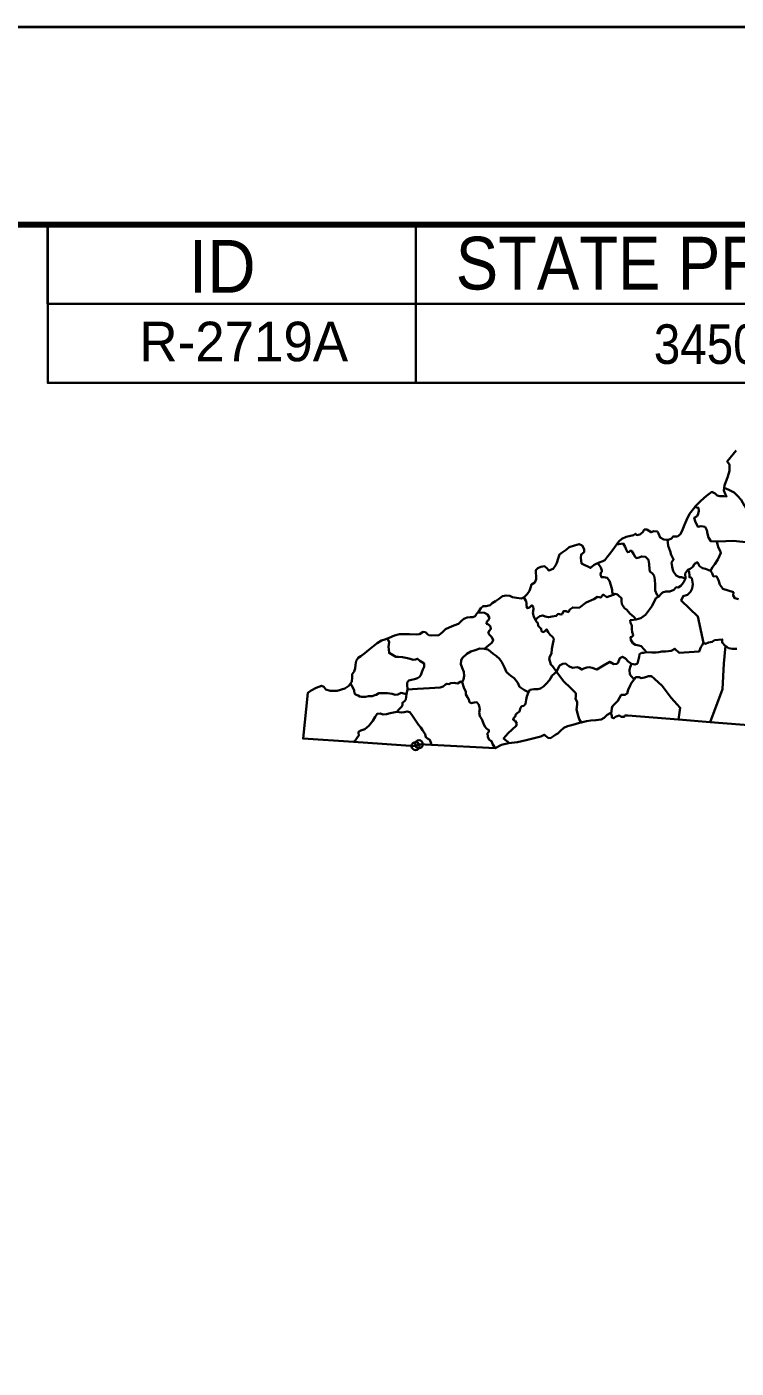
# Model space of a CAD drawing. Extents: x -9.2 to 11.5, y -0.7 to 11.8.
# Drawn here: x 4.396 to 5.741, y 8.457 to 11 of the extents above; entities that cross this region are included whole.
import ezdxf
from ezdxf.enums import TextEntityAlignment as Align

# ---------------------------------------------------------------- set-up
doc = ezdxf.new("R2010")
doc.units = 0
doc.header["$LTSCALE"] = 0.03
doc.header["$PDMODE"] = 32
doc.header["$PDSIZE"] = 0.015
doc.layers.add('1', color=7, linetype='Continuous', lineweight=35)
doc.layers.add('63', color=7, linetype='Continuous', lineweight=35)

msp = doc.modelspace()

# ---------------------------------------------------------------- linework, layer by layer
at = {"layer": '1'}
for p, q in [((4.435, 10.625), (4.435, 10.475)), ((5.1335, 10.626), (5.1335, 10.325)), ((4.435, 10.475), (8.135, 10.475))]:
    msp.add_line(p, q, dxfattribs=at)
at = {"layer": '1', "lineweight": 40}
msp.add_lwpolyline([(-8.5, 11), (8.5, 11), (8.5, 0), (-8.5, 0)], close=True, dxfattribs=at)
at = {"layer": '1', "lineweight": 158}
msp.add_lwpolyline([(0.625, 10.625), (8.135, 10.625), (8.135, 0.375), (0.625, 0.375)], close=True, dxfattribs=at)
at = {"layer": '1'}
msp.add_lwpolyline([(4.4355, 10.625), (8.135, 10.625), (8.135, 10.325), (4.4355, 10.325)], close=True, dxfattribs=at)
at = {"layer": '63'}
for p, q in [((5.5197, 9.8015), (5.5221, 9.8039)), ((5.1181, 9.7438), (5.1157, 9.7349)), ((5.533, 9.7353), (5.5346, 9.7368)), ((5.1332, 9.6364), (5.1395, 9.64)), ((5.1332, 9.6364), (5.1395, 9.64))]:
    msp.add_line(p, q, dxfattribs=at)
for points in [[(5.7412, 10.1971), (5.724, 10.1759), (5.7283, 10.1706), (5.7288, 10.1582), (5.7253, 10.1476), (5.7192, 10.1305), (5.7185, 10.1261), (5.7178, 10.1211), (5.7206, 10.1145), (5.7229, 10.1098), (5.7174, 10.1104), (5.7104, 10.1104), (5.705, 10.1114), (5.7015, 10.1153), (5.695, 10.1183), (5.6849, 10.1107), (5.6742, 10.1013), (5.6632, 10.0904), (5.6625, 10.0894), (5.6527, 10.0766), (5.647, 10.0647), (5.6431, 10.0558), (5.6395, 10.0462), (5.6354, 10.038), (5.6298, 10.0339), (5.6214, 10.034), (5.6187, 10.0301), (5.6126, 10.0273), (5.6112, 10.0274), (5.6042, 10.0279), (5.5968, 10.0317), (5.5941, 10.0393), (5.5918, 10.0434), (5.5848, 10.0436), (5.5797, 10.042), (5.5719, 10.0469), (5.5667, 10.0469), (5.5639, 10.0421), (5.5583, 10.0376), (5.5526, 10.0366), (5.5505, 10.039), (5.5466, 10.0362), (5.5382, 10.0347), (5.5323, 10.0331), (5.5245, 10.0295), (5.5195, 10.0248), (5.5144, 10.0184), (5.5136, 10.0174), (5.5074, 10.0088), (5.5011, 10.0006), (5.4958, 9.9938), (5.4919, 9.989), (5.488, 9.9872), (5.4816, 9.9847), (5.4786, 9.9835), (5.4845, 9.9749), (5.4866, 9.9693), (5.4862, 9.9671), (5.4845, 9.9652), (5.4839, 9.9619), (5.4856, 9.9564), (5.4901, 9.9568), (5.4965, 9.9556), (5.501, 9.9495), (5.5033, 9.9417), (5.5058, 9.9328), (5.5062, 9.9289), (5.5076, 9.9234)], [(5.7185, 10.1261), (5.727, 10.122), (5.7371, 10.1169), (5.7437, 10.1108), (5.7509, 10.1034), (5.7571, 10.0919), (5.7608, 10.0864), (5.7647, 10.0807), (5.7692, 10.0833), (5.7762, 10.0762), (5.782, 10.0696), (5.7904, 10.0663)], [(5.7048, 10.0241), (5.6929, 10.0249), (5.6884, 10.0317), (5.6871, 10.0386), (5.6853, 10.046), (5.6822, 10.052), (5.6746, 10.0534), (5.6686, 10.0519), (5.6635, 10.0626), (5.6614, 10.069), (5.6669, 10.0725), (5.669, 10.077), (5.6704, 10.0827), (5.67, 10.0879), (5.6625, 10.0893)], [(5.2464, 9.883), (5.2487, 9.8867), (5.2489, 9.8871), (5.2524, 9.8912), (5.2567, 9.8982), (5.2612, 9.9019), (5.2669, 9.9015), (5.2745, 9.9038), (5.2786, 9.9075), (5.2846, 9.9112), (5.2903, 9.9153), (5.2983, 9.9204), (5.3049, 9.9221), (5.3117, 9.9213), (5.3172, 9.9188), (5.3248, 9.9176), (5.3343, 9.9162), (5.3394, 9.9189), (5.3447, 9.9244), (5.349, 9.9306), (5.3509, 9.9368), (5.3529, 9.9425), (5.3593, 9.9468), (5.3619, 9.953), (5.3617, 9.9588), (5.3613, 9.9651), (5.3615, 9.97), (5.3652, 9.9739), (5.3707, 9.9764), (5.3777, 9.9773), (5.3822, 9.9738), (5.3859, 9.9691), (5.3943, 9.9722), (5.3984, 9.9787), (5.4009, 9.9841), (5.4033, 9.9919), (5.4058, 9.9995), (5.4109, 10.0032), (5.4185, 10.0087), (5.4246, 10.0133), (5.4345, 10.017), (5.4433, 10.0193), (5.4493, 10.0166), (5.4532, 10.0098), (5.4528, 10.0043), (5.4471, 9.9996), (5.4465, 9.9934), (5.4479, 9.9825), (5.465, 9.9742), (5.4716, 9.9803), (5.4771, 9.9828), (5.4786, 9.9834)], [(5.5945, 9.9202), (5.5904, 9.9237), (5.5873, 9.9315), (5.5873, 9.943), (5.5867, 9.9516), (5.5854, 9.9592), (5.5823, 9.9637), (5.5772, 9.9676), (5.5768, 9.9719), (5.5761, 9.9816), (5.5747, 9.9898), (5.5693, 9.9951), (5.5617, 9.9959), (5.557, 9.9938), (5.5521, 9.993), (5.5494, 9.9953), (5.5465, 10.0008), (5.5434, 10.0057), (5.5409, 10.0071), (5.5381, 10.0045), (5.5352, 10.0038), (5.5327, 10.0092), (5.5309, 10.0141), (5.5269, 10.0205), (5.5228, 10.02), (5.5143, 10.0184)], [(5.6112, 10.0273), (5.612, 10.0163), (5.6157, 10.0059), (5.6182, 9.9991), (5.6209, 9.9929), (5.6225, 9.9901), (5.6184, 9.9843), (5.6195, 9.9765), (5.6216, 9.9683), (5.6275, 9.9597), (5.6339, 9.9566), (5.6378, 9.9568), (5.6452, 9.954)], [(5.7048, 10.0241), (5.7059, 10.0188), (5.7079, 10.0126), (5.7104, 10.0081), (5.7119, 10.003), (5.7098, 9.9972), (5.7062, 9.99), (5.7008, 9.9814), (5.6965, 9.9756), (5.6922, 9.9684)], [(5.7708, 10.0224), (5.7659, 10.0224), (5.7354, 10.0256), (5.7215, 10.0252), (5.7048, 10.0241)], [(5.6922, 9.9685), (5.6828, 9.9726), (5.6774, 9.9736), (5.6719, 9.9773), (5.6677, 9.9851), (5.6622, 9.9818), (5.6587, 9.9766), (5.6542, 9.9727), (5.6495, 9.9709), (5.6522, 9.967), (5.6528, 9.9594), (5.6524, 9.9567), (5.6555, 9.9561), (5.6569, 9.9545), (5.658, 9.9512), (5.659, 9.9434), (5.6576, 9.9354), (5.6543, 9.9288), (5.6486, 9.9231), (5.6406, 9.921), (5.6371, 9.9126), (5.6684, 9.8824), (5.679, 9.8322), (5.6765, 9.8279), (5.6743, 9.8238), (5.671, 9.816), (5.6332, 9.8132), (5.625, 9.821), (5.6182, 9.8173), (5.6131, 9.8167), (5.6073, 9.8158), (5.6003, 9.816), (5.5946, 9.8148), (5.589, 9.8137), (5.581, 9.8137), (5.571, 9.8145), (5.5664, 9.8196), (5.5613, 9.8256), (5.5568, 9.827), (5.55, 9.8284), (5.5453, 9.8315), (5.5413, 9.8377), (5.5409, 9.843), (5.5432, 9.8436), (5.5452, 9.8457), (5.5456, 9.8477), (5.5442, 9.8522), (5.5435, 9.8588), (5.5431, 9.8648), (5.5408, 9.8703), (5.5402, 9.875), (5.5423, 9.8754), (5.5517, 9.8765), (5.5474, 9.8814), (5.5396, 9.8877), (5.5338, 9.8945), (5.5293, 9.8982), (5.5241, 9.9058), (5.5235, 9.9117), (5.5235, 9.9171), (5.5194, 9.921), (5.5161, 9.9236), (5.5109, 9.9248), (5.5076, 9.9234), (5.4959, 9.9186), (5.489, 9.9236), (5.4844, 9.918), (5.4783, 9.9194), (5.4711, 9.9149), (5.4567, 9.9087), (5.4432, 9.8988), (5.4311, 9.8994), (5.4255, 9.8951), (5.4253, 9.8941), (5.4229, 9.8904), (5.4186, 9.8922), (5.4134, 9.8922), (5.411, 9.8863), (5.4087, 9.8862), (5.4034, 9.8871), (5.3999, 9.8834), (5.3923, 9.8819), (5.3892, 9.8817), (5.3855, 9.8807), (5.3791, 9.8821), (5.3742, 9.8843), (5.3691, 9.8829), (5.3642, 9.8794), (5.3603, 9.8759), (5.3572, 9.8816), (5.3557, 9.8888), (5.3571, 9.896), (5.3559, 9.9009), (5.3532, 9.903), (5.3493, 9.8993), (5.3456, 9.8978), (5.3436, 9.9013), (5.3435, 9.9066), (5.3429, 9.9112), (5.3386, 9.9183)], [(5.6495, 9.9708), (5.6446, 9.9634), (5.6452, 9.954)], [(5.7456, 9.9152), (5.7386, 9.9167), (5.7355, 9.9218), (5.7361, 9.9282), (5.7161, 9.9349), (5.7102, 9.9425), (5.7075, 9.9511), (5.7036, 9.9583), (5.698, 9.9581), (5.6966, 9.9603), (5.6955, 9.964), (5.6941, 9.9663), (5.6922, 9.9685)], [(5.6452, 9.954), (5.6415, 9.9464), (5.636, 9.94), (5.6311, 9.9369), (5.6276, 9.9375), (5.6227, 9.9324), (5.6155, 9.9297), (5.6079, 9.9297), (5.6017, 9.9274), (5.5987, 9.9249), (5.5945, 9.9202)], [(5.5517, 9.8764), (5.5601, 9.8791), (5.569, 9.8853), (5.5769, 9.8951), (5.5819, 9.9025), (5.5868, 9.913), (5.5896, 9.9173), (5.5945, 9.9202)], [(5.2464, 9.883), (5.2419, 9.8807), (5.2366, 9.8809), (5.2312, 9.8805), (5.2249, 9.8776), (5.2201, 9.8737), (5.2146, 9.8684), (5.2058, 9.8648), (5.1966, 9.8611), (5.1896, 9.858), (5.184, 9.8527), (5.1771, 9.8465), (5.1635, 9.8459), (5.1586, 9.8469), (5.1563, 9.8481), (5.1518, 9.8522), (5.1477, 9.853), (5.1409, 9.8487), (5.1341, 9.8481), (5.1214, 9.8485), (5.1109, 9.8486), (5.1029, 9.8486), (5.0933, 9.8464), (5.0832, 9.842), (5.08, 9.8406)], [(5.2638, 9.8206), (5.272, 9.8278), (5.2776, 9.8323), (5.2806, 9.8373), (5.2779, 9.843), (5.2732, 9.8471), (5.2711, 9.8514), (5.2732, 9.8557), (5.2761, 9.8586), (5.275, 9.8629), (5.2717, 9.8668), (5.2678, 9.8685), (5.2684, 9.8726), (5.2707, 9.8748), (5.2733, 9.8793), (5.2696, 9.8861), (5.2637, 9.8888), (5.2515, 9.8896)], [(5.4003, 9.7774), (5.3933, 9.7874), (5.3896, 9.7909), (5.3863, 9.8016), (5.3877, 9.8065), (5.3908, 9.8118), (5.3916, 9.8209), (5.3934, 9.8305), (5.3947, 9.8363), (5.3953, 9.8398), (5.393, 9.8439), (5.3883, 9.8473), (5.3843, 9.8525), (5.3815, 9.8576), (5.3778, 9.8539), (5.3745, 9.8527), (5.372, 9.8543), (5.3716, 9.859), (5.3679, 9.8617), (5.3654, 9.8645), (5.3648, 9.8699), (5.3625, 9.8723), (5.3603, 9.8758)], [(5.08, 9.8406), (5.0746, 9.8383), (5.0682, 9.8367), (5.06, 9.8313), (5.0506, 9.8243), (5.0444, 9.8192), (5.0366, 9.8126), (5.0292, 9.8072), (5.0241, 9.8041), (5.0204, 9.7978), (5.019, 9.7904), (5.0188, 9.7838), (5.0164, 9.7778), (5.0129, 9.7729), (5.0131, 9.767), (5.0121, 9.7585), (5.0096, 9.7551), (5.0064, 9.7507), (4.999, 9.7458), (4.9844, 9.7412), (4.9711, 9.741), (4.9632, 9.7439), (4.9591, 9.7486), (4.955, 9.7508), (4.9443, 9.7471), (4.9353, 9.7418), (4.9287, 9.7374), (4.9197, 9.6506), (5.0155, 9.6443), (5.1332, 9.6364)], [(5.08, 9.8406), (5.0828, 9.8334), (5.0818, 9.8246), (5.0822, 9.8198), (5.0828, 9.8131), (5.0892, 9.8092), (5.0954, 9.8057), (5.1009, 9.8055), (5.1081, 9.8053), (5.1176, 9.8033), (5.1231, 9.8019), (5.1287, 9.8), (5.1328, 9.8007), (5.1371, 9.8021), (5.1414, 9.798), (5.1445, 9.7964), (5.1493, 9.7933), (5.1493, 9.7865), (5.1468, 9.7818), (5.1452, 9.7763), (5.1429, 9.7709), (5.1405, 9.7676), (5.1368, 9.7654), (5.131, 9.7635), (5.1255, 9.762), (5.1204, 9.7606), (5.1173, 9.7573), (5.1169, 9.753), (5.1181, 9.7438)], [(5.2638, 9.8206), (5.2548, 9.8212), (5.246, 9.8181), (5.2382, 9.8158), (5.2306, 9.8115), (5.2217, 9.8033), (5.2199, 9.7988), (5.2187, 9.7916), (5.2216, 9.7848), (5.2245, 9.7772), (5.2255, 9.7698), (5.2243, 9.7629), (5.2214, 9.7579)], [(5.347, 9.7387), (5.34, 9.7424), (5.3305, 9.7491), (5.3273, 9.7561), (5.3204, 9.7651), (5.3137, 9.7698), (5.3058, 9.7766), (5.3017, 9.7854), (5.2967, 9.7954), (5.2922, 9.8018), (5.2862, 9.8075), (5.2801, 9.8114), (5.2755, 9.8157), (5.27, 9.8194), (5.2638, 9.8206)], [(5.679, 9.8321), (5.6833, 9.8305), (5.6884, 9.833), (5.6956, 9.8342), (5.7001, 9.8371), (5.7147, 9.8386), (5.7145, 9.8328), (5.7203, 9.8267), (5.7209, 9.8263)], [(5.8284, 9.6712), (5.6921, 9.682), (5.7154, 9.7444), (5.7179, 9.7933), (5.7209, 9.8263), (5.7269, 9.8224), (5.7341, 9.8206), (5.7423, 9.821)], [(5.5429, 9.7922), (5.5361, 9.797), (5.5313, 9.8025), (5.5256, 9.8058), (5.5203, 9.8029), (5.5182, 9.7971), (5.5176, 9.7951), (5.5147, 9.7924), (5.5094, 9.7918), (5.5014, 9.7965), (5.4893, 9.7895), (5.4768, 9.7816), (5.4683, 9.7847), (5.4622, 9.7859), (5.458, 9.7853), (5.4521, 9.7838), (5.4484, 9.7816), (5.4437, 9.7851), (5.4398, 9.7859), (5.4305, 9.785), (5.4241, 9.7883), (5.4176, 9.793), (5.4122, 9.7926), (5.4063, 9.7893), (5.4003, 9.7774)], [(5.571, 9.8145), (5.5652, 9.8132), (5.5617, 9.813), (5.558, 9.8109), (5.5574, 9.8056), (5.5552, 9.7984), (5.5538, 9.7933), (5.5495, 9.7912), (5.5429, 9.7922), (5.5404, 9.7861), (5.539, 9.7809), (5.5398, 9.7723), (5.5433, 9.768), (5.5477, 9.7625), (5.5505, 9.767), (5.5569, 9.7672), (5.561, 9.7654), (5.5674, 9.7662), (5.5746, 9.7691), (5.5805, 9.7693), (5.5863, 9.764), (5.6009, 9.7505), (5.6182, 9.7281), (5.6351, 9.7093), (5.632, 9.6867), (5.6921, 9.6819)], [(5.4003, 9.7774), (5.3923, 9.7706), (5.387, 9.7615), (5.3809, 9.7548), (5.376, 9.7492), (5.37, 9.7457), (5.3649, 9.7441), (5.3577, 9.7442), (5.3501, 9.7434), (5.347, 9.7387)], [(5.4003, 9.7774), (5.4141, 9.7589), (5.4267, 9.7468), (5.4333, 9.7407), (5.4368, 9.7366), (5.4374, 9.7344), (5.437, 9.7304), (5.4364, 9.7259), (5.4395, 9.7206), (5.4393, 9.7151), (5.4383, 9.7056), (5.4408, 9.6964), (5.4437, 9.6876), (5.4469, 9.6814)], [(5.1157, 9.7349), (5.106, 9.7374), (5.0997, 9.7345), (5.0945, 9.7339), (5.0888, 9.7355), (5.0797, 9.7367), (5.0697, 9.7369), (5.0635, 9.7369), (5.0586, 9.7338), (5.0559, 9.7328), (5.051, 9.7311), (5.0438, 9.7313), (5.0383, 9.7301), (5.0307, 9.7298), (5.0272, 9.7302), (5.0243, 9.7323), (5.0194, 9.7343), (5.0175, 9.7364), (5.0169, 9.7417), (5.0148, 9.746), (5.0096, 9.7551)], [(5.1181, 9.7438), (5.1368, 9.7452), (5.1596, 9.7463), (5.1798, 9.7474), (5.1853, 9.7492), (5.1896, 9.7531), (5.1927, 9.7548), (5.1964, 9.754), (5.1999, 9.7558), (5.2065, 9.7563), (5.2128, 9.7553), (5.2188, 9.7587), (5.2214, 9.7579)], [(5.2214, 9.7579), (5.2245, 9.7477), (5.2287, 9.7395), (5.2285, 9.7341), (5.2314, 9.7294), (5.2343, 9.7247), (5.2355, 9.7196), (5.2394, 9.7179), (5.2445, 9.7194), (5.2491, 9.7196), (5.2534, 9.7147), (5.255, 9.7071), (5.2538, 9.7001), (5.2547, 9.6931), (5.2588, 9.6874), (5.2621, 9.6794), (5.2644, 9.6737), (5.2677, 9.67), (5.2722, 9.6669), (5.2722, 9.6636), (5.2697, 9.6609), (5.27, 9.6542), (5.2728, 9.6486), (5.2774, 9.646), (5.2795, 9.6392), (5.2844, 9.6326)], [(5.5477, 9.7625), (5.5426, 9.7567), (5.5399, 9.7512), (5.5362, 9.743), (5.5344, 9.736), (5.5301, 9.7337), (5.5231, 9.7337), (5.5198, 9.7281), (5.5169, 9.7224), (5.5126, 9.7181), (5.5069, 9.7123), (5.5051, 9.7082), (5.5041, 9.6977)], [(5.0977, 9.7015), (5.102, 9.7066), (5.1057, 9.7103), (5.1084, 9.7136), (5.1083, 9.7185), (5.1126, 9.7222), (5.1145, 9.7247), (5.1157, 9.7349)], [(5.311, 9.6423), (5.3, 9.6509), (5.3088, 9.661), (5.3162, 9.6682), (5.3242, 9.675), (5.325, 9.6795), (5.3219, 9.6844), (5.318, 9.6865), (5.3198, 9.6902), (5.3227, 9.6933), (5.3227, 9.6959), (5.3261, 9.6986), (5.3303, 9.7023), (5.3313, 9.7068), (5.3341, 9.712), (5.3382, 9.7128), (5.3417, 9.7165), (5.3429, 9.7239), (5.3442, 9.7305), (5.347, 9.7387)], [(5.0977, 9.7015), (5.0848, 9.6987), (5.078, 9.6969), (5.0714, 9.6965), (5.0657, 9.6981), (5.0605, 9.6979), (5.0564, 9.6919), (5.0523, 9.6841), (5.0448, 9.6749), (5.037, 9.6687), (5.0292, 9.6662), (5.0249, 9.6637), (5.0251, 9.6615), (5.0257, 9.6566), (5.023, 9.6535), (5.0193, 9.6475), (5.0155, 9.6442)], [(5.1635, 9.6387), (5.163, 9.6416), (5.1605, 9.6482), (5.156, 9.6507), (5.1524, 9.6531), (5.1512, 9.6593), (5.1463, 9.6669), (5.1434, 9.672), (5.1386, 9.6767), (5.1335, 9.6841), (5.1273, 9.6941), (5.1223, 9.7009), (5.1174, 9.7021), (5.1115, 9.7009), (5.1065, 9.7), (5.0977, 9.7015)], [(5.1395, 9.64), (5.1635, 9.6387), (5.2844, 9.6326), (5.2959, 9.6386), (5.3094, 9.6421), (5.3263, 9.6436), (5.3427, 9.6475), (5.3579, 9.6517), (5.3708, 9.6544), (5.3768, 9.6577), (5.3768, 9.6583), (5.3797, 9.6562), (5.3846, 9.6521), (5.3893, 9.6517), (5.3945, 9.655), (5.3992, 9.6583), (5.4031, 9.6606), (5.408, 9.6657), (5.4146, 9.6709), (5.4213, 9.6744), (5.4316, 9.6767), (5.4441, 9.6808), (5.4469, 9.6814), (5.457, 9.6837), (5.4657, 9.6847), (5.4753, 9.6854), (5.4854, 9.6866), (5.4909, 9.6899), (5.4965, 9.6957), (5.502, 9.6992), (5.5041, 9.6977), (5.5041, 9.6977), (5.5051, 9.6936), (5.5055, 9.6906), (5.5092, 9.6891), (5.5125, 9.6918), (5.5154, 9.6935), (5.5191, 9.6943), (5.5238, 9.6922), (5.5289, 9.6918), (5.5302, 9.6945), (5.5357, 9.6943), (5.632, 9.6867)]]:
    msp.add_lwpolyline(points, dxfattribs=at)
for p in [(5.1332, 9.6364), (5.1395, 9.64)]:
    msp.add_point(p, dxfattribs=at)

# ---------------------------------------------------------------- texts
at = {"layer": '1'}
for s, height, width, p in [('ID', 0.1, 0.95, (4.7664, 10.496)), ('STATE PROJECT NO.', 0.1, 0.9, (5.8246, 10.502)), ('34501.1.1', 0.075, 0.9, (5.7857, 10.361))]:
    msp.add_text(s, height=height, dxfattribs=dict(at, width=width)).set_placement(p, align=Align.CENTER)
msp.add_text('R-2719A', height=0.075, dxfattribs=at).set_placement((4.8073, 10.366), align=Align.CENTER)

doc.saveas('drawing.dxf')
